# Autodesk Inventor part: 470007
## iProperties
Author: Administrator
Shininess: 74.0
PropertySet Name: _Private Model Information
Created: 2001-04
Part Number: 470007
Document SubType Name: Modeling
Designer: Administrator
Material: Stainless Steel, Austenitic
Description: Formed Bellows, 1"
Control State: 0
Master: False
Checked Out: False
PropertySet Name: Design Tracking Control
Density: 8.03
Volumn: 14.955085843004639
Area: 291.45211941687785
PropertySet Name: Model Information
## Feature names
1. Revolution1
